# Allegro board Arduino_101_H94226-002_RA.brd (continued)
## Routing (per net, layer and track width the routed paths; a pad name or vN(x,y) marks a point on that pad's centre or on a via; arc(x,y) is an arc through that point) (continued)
PWM1/SS11_3V_IO5: length 27.2
  TOP w0.116: U12.G2 37.45,28.37 37.07,28.37 ; U12.A3 37.91,31.22 37.5,31.22 37.34,31.38
  TOP w0.15: v1(38.17,35.37) 37.82,35.02 37.82,34.4 37.02,33.6 37.02,32.53 37.32,32.23 37.32,31.55 v1(37.2,31.42) 37.22,31.4 37.32,31.4 37.34,31.38 ; 37.07,28.37 35.39,30.05 v1(35.17,30.05) ; U11.5 v1(51.74,36.65)
  BOTTOM w0.15: v1(35.17,30.05) 36.52,31.4 37.17,31.4 v1(37.2,31.42) ; v1(51.74,36.65) 51.74,36.53 51.05,35.83 44.84,35.83 44.72,35.95 43.07,35.95 42.32,35.2 38.34,35.2 v1(38.17,35.37)
PWM2/SS12_3V_IO6: length 27.4
  TOP w0.15: U11.4 v1(51.09,36.65) ; v1(34.62,35.1) 34.52,35 34.52,31.55 34.87,31.2 34.87,30.42 34.69,30.24 34.69,29.87 34.97,29.59 35.43,29.59 36.93,28.09 U12.G1
  BOTTOM w0.15: v1(34.62,35.1) 35.97,35.1 36.47,35.6 37.72,35.6 37.95,35.83 38.36,35.83 38.68,35.5 42.17,35.5 42.92,36.25 44.87,36.25 44.99,36.13 50.7,36.13 51.09,36.53 v1(51.09,36.65)
PWM3/SS13_3V_IO9: length 12.8
  TOP w0.116: 37.12,28.94 37.45,28.94 U12.F2
  TOP w0.15: 37.12,28.94 36.93,28.94 35.17,30.7 35.17,31.35 34.82,31.7 34.82,34.65 35.09,34.92 35.09,35.78 35.4,36.08 37.25,36.08 37.65,36.47 37.65,37.65
RST_SKETCH: length 96.2
  TOP w0.15: R23.2 29.31,44.59 30.17,45.45 33.47,45.45 v1(33.72,45.2) 33.74,45.17 U14.18 33.74,42.5 33.21,41.97 32.56,41.97 32.07,41.48 v1(32.07,41.32) ; J10.3 33.02,3.34 31.57,4.79 31.57,5.2 32.17,5.8 32.17,16.05 30.67,17.55 30.67,30.85 31.77,31.95 31.77,35.9 31.07,36.6 v1(31.07,39.3)
  BOTTOM w0.15: v1(33.72,45.2) 33.87,45.05 35.97,45.05 36.12,44.9 53.55,44.9 62.77,35.68 62.77,33.58 64.64,31.7 64.64,29.03 65.02,28.65 65.02,26.79 J12.5 ; v1(32.07,41.32) 32.07,40.3 v1(31.07,39.3)
RST_SKETCH_3V: length 25.3
  TOP w0.116: 45.82,28.33 45.87,28.38 46.47,28.38 U12.F22
  TOP w0.15: U14.3 v1(33.74,36.64) ; 45.82,28.33 45.72,28.33 45.6,28.2 44.28,28.2 43.76,28.72 43.76,31.21 44.06,31.51 44.06,33.74 44.52,34.2 44.52,37.65 v1(44.27,37.9)
  BOTTOM w0.15: v1(33.74,36.64) 34.98,36.64 35.76,37.42 36.01,37.42 36.68,38.09 39.58,38.09 39.92,37.75 41.22,37.75 41.27,37.8 44.17,37.8 v1(44.27,37.9)
RXD1/SS9_3V_IO0: length 24.7
  TOP w0.116: 45.87,26.64 46.05,26.64 46.07,26.66 46.46,26.66 U12.K22
  TOP w0.15: U11.10 v1(54.99,36.65) ; v1(43.45,34.25) 43.49,34.21 43.49,31.76 43.2,31.47 43.2,28.3 43.15,28.25 43.15,27.56 43.5,27.2 44.15,27.2 44.64,26.7 45.24,26.7 45.31,26.64 45.87,26.64
  BOTTOM w0.15: v1(43.45,34.25) 43.45,34.22 43.56,34.11 44.28,34.11 44.5,34.33 52.8,34.33 54.99,36.53 v1(54.99,36.65)
RXLED: length 12.3
  TOP w0.116: U12.C3 37.91,30.08 37.02,30.08
  TOP w0.15: v1(29.57,33.25) 29.41,33.25 D15.K ; v1(35.58,32.05) 35.77,31.86 35.77,30.9 36.59,30.08 37.02,30.08
  BOTTOM w0.15: v1(35.58,32.05) 35.4,32.23 30.44,32.23 29.57,33.1 v1(29.57,33.25)
SP0_CLK_MEM: length 20.5
  TOP w0.15: v1(41.12,27.55) 41.09,27.53 41.09,26.67 43.87,23.9 43.87,22.42 44.12,22.17 44.12,19.1 43.22,18.2 40.32,18.2 40.17,18.05 40.17,17.24 U201.6 ; v1(39.75,30.84) 39.69,30.78 39.69,30.7 39.36,30.37 U12.C4
  BOTTOM w0.15: v1(39.75,30.84) 39.69,30.78 39.69,30.7 39.4,30.41 39.4,29.23 41.07,27.55 v1(41.12,27.55)
SP0_CS0_MEM: length 29.9
  TOP w0.116: U12.B3 38.48,31.22 38.76,31.22 39.02,31.48 39.02,31.83 v1(39.05,31.85)
  TOP w0.15: U201.1 37.56,11.3 39.47,13.2 39.47,18.05 39.92,18.5 43.02,18.5 43.82,19.3 43.82,22.03 43.57,22.28 43.57,23.7 40.62,26.65 v1(40.62,27.08)
  BOTTOM w0.15: v1(40.62,27.08) 40.62,27.6 39.12,29.1 39.12,31.7 39.05,31.78 v1(39.05,31.85)
SP0_MISO_MEM: length 25.9
  TOP w0.15: v1(39.87,29.58) 39.85,29.56 39.71,29.56 39.48,29.79 38.65,29.79 U12.D4 ; v1(43.02,17.7) 43.22,17.7 44.42,18.9 44.42,22.28 44.17,22.53 44.17,24.07 41.57,26.67 v1(41.57,27.08) ; v1(42.97,16) 42.62,15.65 42.62,14.65 38.84,10.87 U201.2
  BOTTOM w0.15: v1(43.02,17.7) 43.22,17.5 43.22,16.25 v1(42.97,16) ; v1(41.57,27.08) 41.59,27.1 41.59,27.73 41.3,28.03 40.99,28.03 39.87,29.15 v1(39.87,29.58)
SP0_MOSI_MEM: length 20.6
  TOP w0.116: U12.D3 38.48,30.08 38.99,30.08 38.99,30.08 39.07,30.08
  TOP w0.15: 39.07,30.08 39.62,30.08 39.72,30.17 39.83,30.17 v1(39.87,30.21) ; v1(41.82,28.15) 41.82,28.15 42.03,27.94 42.03,26.64 44.47,24.2 44.47,22.62 44.72,22.38 44.72,18.65 43.27,17.2 42.82,17.2 42.22,17.8 41.52,17.8 41.38,17.66 U201.5
  BOTTOM w0.15: v1(39.87,30.21) 39.87,30.21 40.06,30.21 40.33,29.94 40.33,29.09 41.09,28.33 41.65,28.33 41.82,28.15 v1(41.82,28.15)
SP0_WP_MEM~: length 27.9
  TOP w0.15: v1(43.67,16) 43.67,13.24 R62.1 42.29,12.84 40.11,10.65 U201.3 ; v1(40.07,27.5) 40.07,26.72 43.27,23.52 43.27,22.17 43.52,21.92 43.52,19.5 43.02,19 v1(42.72,19) ; v1(38.42,31.98) 38.45,31.95 38.45,31.92 38.55,31.83 38.55,31.6 U12.A4
  BOTTOM w0.15: v1(42.72,19) 42.72,18.73 43.52,17.92 43.52,16.15 v1(43.67,16) ; v1(38.42,31.98) 38.42,31.65 38.84,31.23 38.84,28.98 40.07,27.75 v1(40.07,27.5)
TRIG_TRUE_D: length 45.3
  TOP w0.25: R75.1 17.42,37.89 U202.4 ; R75.1 17.31,37.74 16.57,37 16.57,35.6 15.87,34.9 U13.C3 ; R75.1 C55.1 19.89,37.74 R81.2 20.13,37.24 20.77,36.6 v1(22.02,36.6) ; v1(29.42,30.35) 29.52,30.25 29.52,17.05 30.87,15.7 v1(30.87,15.5) ; U10.13 v1(22.32,16.05)
  BOTTOM w0.25: v1(30.87,15.5) 22.87,15.5 v1(22.32,16.05) ; v1(29.42,30.35) 29.42,30.55 23.37,36.6 v1(22.02,36.6)
TXD1/SS8_3V_IO1: length 22.6
  TOP w0.15: v1(44.05,34.58) 43.97,34.5 43.97,34.08 43.77,33.88 43.77,31.62 43.48,31.33 43.48,28.19 43.42,28.13 43.42,27.69 43.64,27.47 44.3,27.47 44.77,27 45.34,27 45.42,26.91 45.96,26.91 45.99,26.95 U12.J21 ; U11.9 v1(54.34,36.65)
  BOTTOM w0.15: v1(44.05,34.58) 44.1,34.63 52.45,34.63 54.34,36.53 v1(54.34,36.65)
TXLED: length 21.1
  TOP w0.15: U12.D21 46.27,29.83 45.59,29.83 45.17,30.25 v1(44.87,30.25) ; v1(30.67,34.28) D14.K
  BOTTOM w0.15: v1(30.67,34.28) 32.12,32.83 36.17,32.83 36.39,33.05 38.86,33.05 39,32.91 39.48,32.91 40.15,32.24 40.15,31.89 40.82,31.22 41.3,31.22 41.65,30.88 43.7,30.88 44.32,30.25 v1(44.87,30.25)
USB_5P00_PWR: length 13.7
  TOP w0.3: U13.A3 14.33,35.34 ; U13.B3 15.17,35.46 C18.1
  TOP w0.5: 14.33,35.34 13.16,35.34
  TOP w0.7: 13.16,35.9 13.46,36.2 C18.1 ; 13.16,35.9 v1(12.17,35.9) 11.47,35.9 10.52,36.85 J17.1 ; 13.16,35.9 C42.1 R12.1
  BOTTOM w0.5: TPB19.1 12.87,35.35 12.72,35.35 v1(12.17,35.9)
USBDN_CONN: length 45.1
  TOP w0.116: U12.J23 47.48,26.66 47.86,26.66 48.05,26.48
  TOP w0.15: v1(48.58,26.22) 48.58,26.23 48.57,26.23 48.57,26.25 48.47,26.35 48.17,26.35 48.05,26.48
  TOP w0.889: R32.2 15.76,38.05 v1(16.42,38.05)
  BOTTOM w0.45: 48.15,26.2 48.54,26.2 48.56,26.22 v1(48.58,26.22)
  BOTTOM w0.5: 47.74,24.94 47.78,24.99 47.78,25.26 47.84,25.32 47.84,25.32 47.84,25.9 48.15,26.2
  BOTTOM w0.889: 47.74,24.94 46.28,23.48 44,23.48 43.43,24.05 38.32,24.05 37.62,24.75 27.72,24.75 24.57,27.9 24.57,30.56 17.08,38.05 v1(16.42,38.05) 15.52,38.05 TPB17.1
USBDP_CONN: length 43.4
  TOP w0.102: U12.J24 48.07,26.95
  TOP w0.15: 48.07,26.95 48.23,26.95 v1(48.34,26.83)
  TOP w0.889: R31.2 15.61,39.14 15.68,39.07 v1(16.42,39.07)
  BOTTOM w0.45: 47.87,26.83 v1(48.34,26.83)
  BOTTOM w0.5: 47.02,25.66 47.02,25.98 47.87,26.83
  BOTTOM w0.889: 47.02,25.66 45.86,24.5 44.42,24.5 43.85,25.07 38.74,25.07 38.04,25.77 28.14,25.77 25.59,28.32 25.59,30.98 17.51,39.07 v1(16.42,39.07) 15.5,39.07 TPB18.1
V_1P8_ESR3: length 8.4
  TOP w0.3: U12.P3 38.19,23.84 38.19,23.84 38.19,23.67
  TOP w0.35: 37.61,22.94 37.61,23.09 38.19,23.67
  TOP w0.4: 37.61,22.94 37.22,22.55
  TOP w0.5: C29.1 C30.1 35.53,19.64 35.77,19.88 L12.1 35.77,21.55 36.77,22.55 37.22,22.55
V_3P3SRC_VDD1: length 34.9
  TOP w0.65: 26.31,20.16 R63.2 28.07,19.96 28.07,18.4 ; 26.57,26.62 27.84,26.62 27.87,26.66 R58.2
  TOP w1: J10.2 30.48,3.34 29.57,4.25 29.57,15.2 28.17,16.6 28.17,18.3 U17.2
  BOTTOM w0.8: J10.2 30.51,2.54 32.17,4.2 33.9,4.2 J10.4
  vias: v1(19.57,25.2) v1(19.57,24.2) v1(19.57,23.2) v1(19.57,22.2) v1(19.57,21.2) v1(19.57,20.2) v1(20.32,25.7) v1(20.32,24.7) v1(20.32,23.7) v1(20.32,22.7) v1(20.32,21.7) v1(20.32,20.7) v1(20.32,19.7) v1(20.87,26.6) v1(21.32,25.95) v1(21.32,19.5) v1(21.82,26.6) v1(22.32,25.95) v1(22.32,19.5) v1(22.82,26.6) v1(23.32,25.95) v1(23.32,19.5) v1(23.82,26.6) v1(24.32,25.95) v1(24.32,19.5) v1(25.32,19.5) v1(26.32,19.5) v1(27.07,23.45) v1(27.07,22.5) v1(27.07,21.5) v1(27.07,20.6) v1(27.07,19.7)
V_3P5_VREFA: length 56.6
  TOP w0.35: v1(49.8,39.2) U11.2 49.8,36.38 52.15,34.02 v1(52.15,32.85) ; v1(52.07,22.48) 52.47,22.08 52.47,17.1 53.07,16.5 53.67,16.5 54.01,16.16 U15.2 54.01,14.84 ; U14.2 v1(33.09,39.12)
  TOP w0.5: v1(48.17,12.44) R34.2 R33.2 C43.1 ; 54.01,14.84 54.01,14.28 53.33,13.6 v1(51.67,13.6)
  BOTTOM w0.35: v1(52.07,22.48) 52.07,22.8 52.32,23.05 52.32,28.1 51.37,29.05 51.37,29.72 52.52,30.86 52.52,31.4 52.33,31.59 52.33,32.14 52.15,32.32 v1(52.15,32.85) ; v1(33.09,39.12) 33.73,39.75 40.92,39.75 41.37,39.3 49.7,39.3 v1(49.8,39.2)
  BOTTOM w0.5: v1(48.17,12.44) 50.51,12.44 v1(51.67,13.6)
V_5P00SRC_VDD1: length 180.3
  TOP w0.2: v1(21.37,16.7) 21.32,16.65 U10.14
  TOP w0.3: U13.B1 U13.A1 14.43,33.76
  TOP w0.5: v1(55.37,9.65) 55.76,9.26 R27.1 ; R28.1 30.21,40.76 29.57,41.4 v1(29.57,42.15) ; v1(47.43,42.48) 47.23,42.69 47.23,44.24 46.03,45.44 R29.1 ; C39.1 14.43,33.76
  TOP w0.6: R57.2 v1(13.67,31.4)
  TOP w0.65: v1(51.87,31.1) 52.12,31.1 53.62,32.6 v1(54.47,32.6) ; J12.2 66.17,30.98 65.34,31.8 60.67,31.8 v1(59.87,32.6)
  TOP w0.7: C39.1 R57.2 C49.1 14.43,28.91 ; R33.1 47.33,9.49 v1(47.37,9.45)
  TOP w0.8: v1(47.37,9.45) v1(47.37,5) v1(46.72,5)
  TOP w1: U17.3 16.46,20.42 14.43,22.44 14.43,28.91
  BOTTOM w0.2: v1(21.37,16.7) 20.87,17.2 19.67,17.2 v1(19.17,16.7)
  BOTTOM w0.5: v1(29.57,42.15) 30.51,42.15 31.08,42.73 33.74,42.73 34.39,42.08 36.8,42.08 37.07,42.35 41.18,42.35 42.99,40.54 44.29,40.54 45.42,41.67 46.63,41.67 v1(47.43,42.48)
  BOTTOM w0.6: v1(29.57,42.15) 27.17,42.15 26.42,41.4 12.67,41.4 11.07,39.8 11.07,35.2 13.67,32.6 v1(13.67,31.4)
  BOTTOM w0.65: v1(54.47,32.6) v1(59.87,32.6) ; v1(51.87,31.1) 50.75,29.98 50.75,28.76 51.62,27.89 51.62,25.9
  BOTTOM w0.8: 51.62,25.9 51.62,23.4 51.27,23.05 51.27,22.05 52.27,21.05 52.27,16 55.5,12.77 55.5,9.78 v1(55.37,9.65) 55.17,9.45 v1(47.37,9.45) ; 38.1,3.77 38.83,4.5 46.22,4.5 v1(46.72,5) v1(47.37,5) ; v1(15.67,17.7) v1(16.27,17.7) v1(15.67,18.3) v1(15.67,17.7)
  BOTTOM w1.5: v1(15.67,17.7) 14.46,16.49 14.46,10.81 15.52,9.75 15.52,7.55 18.47,4.6 25.57,4.6 26.17,5.2 29.72,5.2 31.02,6.5 35.37,6.5 38.1,3.77 J10.5
VSYS: length 32.4
  TOP w0.25: U12.N4 39.11,24.67 39.24,24.53 ; 39.42,25.7 39.37,25.75 38.97,25.75 38.91,25.81 U12.L4
  TOP w0.3: U12.P2 37.74,23.95
  TOP w0.35: 37.74,23.95 37.05,23.25
  TOP w0.5: 34.72,22.4 35.57,23.25 37.05,23.25 ; 34.72,22.4 34.52,22.2 C32.1 C31.1 34.17,20.9 34.72,21.45 v1(34.72,21.5) 34.72,22.4 ; 39.24,24.53 39.52,24.25 v1(39.52,22.25) 39.52,21.59 C33.1 ; 39.42,25.7 39.52,25.7 40.52,24.7 40.52,22.36 v1(40.63,22.25) C25.1 C26.1
  TOP w0.6: R63.1 v1(28.27,22.2)
  BOTTOM w0.6: v1(28.27,22.2) 29.27,22.2 29.97,21.5 v1(34.72,21.5) 38.77,21.5 v1(39.52,22.25) v1(40.63,22.25)
N137369: length 9.4
  TOP w0.3: ESD11.1 13.27,39.06
  TOP w0.889: R31.1 14.19,39.06 12.65,39.06 11.03,40.67 7.85,40.67 J17.3
N350266: length 21.1
  TOP w0.116: U12.E23 47.48,29.51 47.83,29.51 47.97,29.65 47.97,29.8 48.07,29.9
  TOP w0.15: R30.2 50.78,32.44 v1(50.17,33.05) ; 48.07,29.9 48.18,30.01 48.33,30.01 49.39,31.07 49.39,31.55 48.97,31.98 48.97,32.7 v1(48.77,32.9) ; v1(39.83,33.28) 39.86,33.24 39.86,31.99 38.8,30.94 U12.B4
  BOTTOM w0.15: v1(39.83,33.28) 39.83,32.99 40.09,32.73 41.11,32.73 42.06,31.78 46.05,31.78 46.27,32 46.27,32.35 46.92,33 48.27,33 48.37,32.9 v1(48.77,32.9) 50.02,32.9 v1(50.17,33.05)
N352539: length 12.5
  TOP w0.116: 45.87,25.48 46.1,25.48 46.14,25.52 46.46,25.52 U12.L22
  TOP w0.15: R24.2 48.74,22.64 v1(48.74,23.42) ; v1(44.65,25.48) 44.97,25.15 45.5,25.15 45.82,25.48 45.87,25.48
  BOTTOM w0.15: v1(48.74,23.42) 48.8,23.47 48.8,24.37 49.07,24.64 49.07,26.78 48.55,27.3 47.67,27.3 45.52,25.15 44.97,25.15 v1(44.65,25.48)
N364156: length 3.8
  TOP w0.3: U12.P4 38.64,23.42
  TOP w0.35: 38.64,23.42 38.16,22.94 38.16,22.59
  TOP w0.4: 38.16,22.59 37.97,22.4
  TOP w0.5: 37.97,22.4 L12.2
N380754: length 5.8
  TOP w0.25: U12.K1 36.79,26.38
  TOP w0.3: 36.55,26.51 36.69,26.38 36.79,26.38
  TOP w0.4: C35.1 33.57,30 34.7,28.88 35.12,28.88 35.71,28.29 35.71,27.35 36.55,26.51
N385382: length 1.2
  TOP w0.9: 60.77,20.34 RLC11.2
  TOP w1.016: RLC10.2 60.77,20.34
N385442: length 3.5
  TOP w0.6: R19.2 58.37,16.94
  TOP w1.016: RLC10.1 C37.2 58.37,16.94
N441562: length 7
  TOP w0.3: 13.27,38.04 ESD10.1
  TOP w0.889: J17.2 8.83,39.66 10.61,39.66 12.23,38.04 14.19,38.04 R32.1
N463771: length 4.2
  TOP w0.116: U12.N2 37.45,24.38 36.87,24.38
  TOP w0.15: C45.1 34.76,24.25 36.45,24.25 36.58,24.38 36.87,24.38
N498391: length 6.8
  TOP w0.116: U12.H23 47.48,27.8 48.07,27.8
  TOP w0.2: U12.G22 46.75,28.02 47.2,27.57 U12.H23
  TOP w0.25: 48.07,27.8 48.16,27.72 48.82,27.72 49.09,27.45 49.17,27.45
  TOP w0.4: 49.17,27.45 49.87,27.45 50.13,27.19 R35.1 C20.1
N521217: length 16.6
  TOP w0.25: U12.K4 38.95,26.38 v1(39.06,26.26)
  TOP w0.5: R59.1 26.21,29.3 v1(26.47,29.3) 27.31,29.3 C17.1
  BOTTOM w0.5: v1(26.47,29.3) 26.47,28.6 28.47,26.6 38.48,26.6 38.81,26.26 v1(39.06,26.26)
N616057: length 5.6
  TOP w0.25: U12.L1 37.09,25.81 37.04,25.75
  TOP w0.3: 37.04,25.75 36.52,25.75 36.37,25.9
  TOP w0.4: 36.37,25.9 35.17,27.1 35.17,28.05 34.87,28.35 34.48,28.35 34.47,28.35 34.12,28.7 C48.1
N656910: length 5.3
  TOP w0.35: U15.19 54.01,10.39 54.22,10.6 54.66,10.6 ; C51.1 R27.2 56.12,10.53 56.05,10.6 54.66,10.6 ; 54.66,10.6 U15.20
N656990: length 5.7
  TOP w0.35: 49.14,44.52 49.61,44.52 49.8,44.33 U11.19 ; 49.14,44.52 48.43,45.23 C53.1 R29.2 ; 49.14,44.52 U11.20
N657094: length 5.6
  TOP w0.35: C52.1 R28.2 31.98,42.04 32.45,42.5 ; 32.45,42.5 32.97,42.5 33.09,42.62 U14.19 ; 32.45,42.5 32.45,43.55
N692018: length 3.7
  TOP w0.4: SH10.1 17.71,32.4 R73.2 17.57,33.1 18.11,33.64 R74.1
N692192: length 1.5
  TOP w0.3: R74.2 16.33,34.5 U13.C2
N704436: length 1.4
  TOP w0.25: C15.1 23.56,13.95 U10.9
N704444: length 8.6
  TOP w0.25: v1(21.87,12.7) 21.82,12.75 U10.8 ; v1(16.67,13.9) 16.41,13.9 R71.1 15.97,14.34 R70.2
  BOTTOM w0.25: v1(16.67,13.9) 20.87,13.9 21.87,12.9 v1(21.87,12.7)
N724575: length 28.2
  TOP w0.15: v1(11.57,48) 11.18,48 10.33,47.15 SW12.2 ; R23.1 C41.1 v1(26.91,45.6)
  BOTTOM w0.15: v1(11.57,48) 12.37,47.2 23.77,47.2 25.37,45.6 v1(26.91,45.6)
N724587: length 11.3
  TOP w0.15: SW10.4 v1(4.63,24.83) ; R13.1 C19.1 9.08,26.07 9.07,26.06 v1(9.07,24.83) SW10.3
  BOTTOM w0.15: v1(4.63,24.83) v1(9.07,24.83)
N726409: length 1.2
  TOP w0.25: R10.2 59.47,36.61 59.48,36.61 D10.A
N726427: length 1.4
  TOP w0.15: R15.2 26.69,36.58 D14.A
N726455: length 1.3
  TOP w0.15: D15.A 26.62,34.29 R16.2
N765836: length 4
  TOP w0.25: R83.2 R82.1 C54.1 19.37,41.4 U202.1
N7255913: length 2.2
  TOP w0.15: R14.1 26.01,41.06 25,40.05 25,40.05 24.59,39.65 U16.4
N7256071: length 1.5
  TOP w0.15: R14.2 27.34,42.34 D13.A

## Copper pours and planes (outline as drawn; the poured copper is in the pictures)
GND on TOP (solid shape): 61.06,21.89 59.82,21.89 59.82,22.89 61.06,22.89
GND on TOP (solid shape): 26.97,17.7 26.97,17.1 26.87,17 21.67,17 21.57,17.1 21.17,17.1 20.97,16.9 20.97,15.65 21.02,15.6 21.92,15.6 21.97,15.55 21.97,13.8 21.52,13.8 21.52,13.05 20.17,13.05 20.17,16.6 20.47,16.9 20.47,18.3 20.97,18.8 25.87,18.8
GND on TOP (solid shape): 50.34,23.3 50.41,23.29 50.45,23.23 50.45,20.64 51.47,19.62 51.47,16.42 51.6,16.28 51.61,16.23 51.58,16.21 51.55,16.21 51.17,16.58 51.17,19.08 50.17,20.08 50.17,21.44 50.3,21.57 50.3,23.28
GND on TOP (solid shape): 51.85,8.48 52,8.34 51.99,8.32 52.02,8.09 52.17,7.93 52.17,7.85 52.18,7.77 52.23,7.71 53.24,6.7 58.13,6.7 61.06,3.77 61.06,3.53 61.04,3.47 60.98,3.45 60.73,3.42 60.5,3.33 60.48,3.31 57.68,6.1 53.19,6.1 51.79,7.51 51.8,7.53 51.77,7.76 51.61,7.93 51.61,8.75 51.85,8.75
GND on TOP (solid shape): 49.87,22.96 49.89,22.93 49.89,21.73 49.77,21.61 49.77,19.92 50.77,18.92 50.77,17.33 50.72,17.26 50.64,17.28 50.42,17.38 50.19,17.34 50.11,17.34 50.07,17.4 50.07,17.62 50.1,17.63 50.2,18.34 49.66,17.86 49.67,17.85 49.67,16.32 49.71,16.28 49.71,16.23 49.68,16.21 49.65,16.21 49.42,16.44 49.42,21.53 49.77,21.89 49.77,22.92 49.8,22.94 49.83,22.96
GND on TOP (solid shape): outline of 184 points within 62.53,4.12 68.08,11.12
GND on TOP (solid shape): outline of 184 points within 62.54,4.12 68.08,11.12
GND on TOP (solid shape): 38.09,36.49 40.1,34.49 40.1,33.69 40.06,33.63 39.99,33.62 39.48,33.44 39.66,32.93 39.66,32.08 39.49,31.91 39.42,31.89 39.36,31.94 39.16,32.16 38.87,32.13 38.8,32.12 38.76,32.16 38.24,32.31 38.08,31.79 38.09,31.74 38.06,31.7 37.98,31.6 37.96,31.49 37.96,31.47 37.85,31.36 37.56,31.36 37.52,31.39 37.52,31.47 37.52,32.31 37.22,32.61 37.22,33.52 38.02,34.32 38.02,34.94 38.09,35 38.1,34.99 38.44,35.64 37.79,35.3 37.8,35.28 37.63,35.12 37.61,35.14 37.39,35.23 37.16,35.17 37.09,35.16 37.05,35.22 36.6,35.52 36.29,35.08 36.3,35.06 35.86,34.63 35.86,32.46 35.82,32.39 35.75,32.39 35.59,32.43 35.43,32.4 35.36,32.41 35.32,32.47 35.32,34.42 35.62,34.72 35.62,35.22 35.65,35.23 35.91,35.43 35.92,35.76 35.92,35.84 35.98,35.87 37.33,35.87 37.85,36.39 37.85,36.87 38.09,36.87
GND on TOP (solid shape): outline of 10907 points within 0.5,0.5 68.08,52.84
GND on BOTTOM (solid shape): 48.05,31.93 48.07,31.9 48.05,31.88 47.94,31.6 48.05,31.33 48.08,31.3 47.67,30.88 47.67,29.32 48.62,28.37 48.62,28.14 48.63,28.12 48.64,28.08 48.61,28.06 48.49,28.06 48.49,28.06 47.36,28.06 47.34,28.05 46.91,27.63 45.55,27.63 45.52,27.66 45.53,27.68 45.48,27.94 45.26,28.11 45.21,28.16 45.23,28.24 45.54,28.54 45.54,29.16 45.54,29.21 45.54,29.27 45.54,29.38 45.95,29.79 45.95,30.44 47.15,31.64 47.15,31.99 47.31,32.15 47.83,32.15
GND on BOTTOM (solid shape): 40.44,30.73 40.49,30.8 40.57,30.79 40.64,30.73 41.1,30.73 41.45,30.37 43.51,30.37 44.14,29.74 44.14,29.72 44.16,29.54 44.26,29.39 44.28,29.34 44.26,29.28 44.14,29.06 44.19,28.81 43.99,28.6 43.59,28.6 43.29,28.3 43.05,28.3 42.2,29.15 41.75,29.15 41.74,29.18 41.4,29.48 41.02,29.24 40.96,29.2 40.89,29.22 40.82,29.28 40.82,30.24 40.44,30.62
GND on BOTTOM (solid shape): outline of 7217 points within 0.5,0.5 68.08,52.84
(no net) on TOP: 1,0.5 0.65,0.65 0.5,1 0.5,52.34 0.65,52.69 1,52.84 64.31,52.84 65.54,51.61 65.54,39.42 68.08,36.88 68.08,5.29 65.54,2.75 65.54,1 65.39,0.65 65.04,0.5 ; 23 cut-outs
(no net) on BOTTOM: 1,0.5 0.65,0.65 0.5,1 0.5,52.34 0.65,52.69 1,52.84 64.31,52.84 65.54,51.61 65.54,39.42 68.08,36.88 68.08,5.29 65.54,2.75 65.54,1 65.39,0.65 65.04,0.5 ; 19 cut-outs
DC_IN_5V_20V on TOP (solid shape): 22.47,10 23.07,10 23.42,9.65 23.42,8.75 23.07,8.4 22.47,8.4 22.27,8.2 20.07,8.2 20.07,10.2 22.27,10.2
DC_IN_5V_20V_FIL on TOP (solid shape): 27.77,8.4 24.37,8.4 24.02,8.75 24.02,9.65 24.37,10 25.37,10 25.77,10.4 27.77,10.4
Net_127 on TOP (solid shape): outline of 208 points within 14.59,-7.41 19.41,-2.59
Net_127 on TOP (solid shape): outline of 208 points within 16.59,56.93 21.41,61.75
Net_128 on BOTTOM (solid shape): outline of 208 points within 10.59,-7.41 15.41,-2.59
Net_128 on BOTTOM (solid shape): outline of 208 points within 12.59,56.93 17.41,61.75
Net_129 on BOTTOM (solid shape): outline of 208 points within 8.59,-71.75 13.41,-66.93
Net_130 on TOP (solid shape): outline of 208 points within 12.59,-71.75 17.41,-66.93
Net_131 on TOP (solid shape): outline of 208 points within 121.75,-71.75 126.57,-66.93
Net_132 on BOTTOM (solid shape): outline of 208 points within 125.75,-71.75 130.57,-66.93
Net_133 on BOTTOM (solid shape): outline of 208 points within 121.75,56.93 126.57,61.75
Net_133 on BOTTOM (solid shape): outline of 208 points within 123.75,-7.41 128.57,-2.59
Net_134 on TOP (solid shape): outline of 208 points within 117.75,56.93 122.57,61.75
Net_134 on TOP (solid shape): outline of 208 points within 119.75,-7.41 124.57,-2.59
V_3P3SRC_VDD1 on TOP (solid shape): 22.82,26.95 26.82,26.95 27.07,26.7 27.07,26.2 27.57,25.7 27.57,19.45 27.32,19.2 20.12,19.2 19.12,20.2 19.12,21.2 18.42,21.9 17.57,21.9 17.32,22.15 17.32,23.45 17.57,23.7 18.57,23.7 19.07,24.2 19.07,25.45 19.57,25.95 20.07,25.95 20.57,26.45 20.57,27.7 20.82,27.95 21.82,27.95
V_3P3SRC_VDD1 on BOTTOM (solid shape): 27.57,23.45 27.57,19.45 27.32,19.2 20.07,19.2 19.07,20.2 19.07,25.45 20.57,26.95 24.07,26.95
V_5P00SRC_VDD1 on TOP (solid shape): 18.62,20.95 18.62,19.95 19.87,18.7 19.87,17.15 19.47,16.75 19.47,16.6 19.27,16.4 18.82,16.4 18.72,16.3 15.57,16.3 14.37,17.5 14.37,18.4 15.57,19.6 15.57,21.2 15.77,21.4 18.17,21.4
N385382 on TOP (solid shape): 67.61,12.13 63.06,12.13 63.06,17.13 63.58,17.13 63.58,12.65 67.06,12.65 67.06,20.13 60.43,20.13 60.43,20.66 67.06,20.66 67.06,22.13 60.06,22.13 60.06,22.65 67.61,22.65
N544606 on TOP (solid shape): 26.92,16.25 26.92,15.85 27.97,14.8 27.97,12.5 27.67,12.2 25.77,12.2 25.37,12.6 25.37,13.4 24.47,14.3 22.12,14.3 22.12,15.6 22.17,15.65 22.57,15.65 23.32,16.4 26.77,16.4
N545273 on TOP (solid shape): 20.02,14.3 17.57,14.3 17.07,14.8 17.07,15.45 17.22,15.6 20.02,15.6

Small or netless copper shapes (teardrops, artwork), in the pictures only: 4 on TOP, 1 on BOTTOM

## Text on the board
BOTTOM: H94226-002 REV A
Ref Des/Silkscreen Bottom: 3 | 4 | 2 | 1
Ref Des/Silkscreen Top: MP H92726-002 | 180 Degree | 4 | 2 | 1 | 3 | 0 Degree
DIMENSION: D13 | D14 | D15 | D10 | ESD10 | ESD11 | U202 | D17 | U10 | L12 | J18 | U13 | L10 | SH10 | U16 | D18 | R13 | C19 | C42 | R12 | C11 | R31 | R32 | C18 | C39 | R57 | C49 | R71 | R74 | C36 | C14 | C13 | R81 | C54 | R82 | R83 | C50 | L13 | R59 | R15 | R16 | C41 | R23 | C35 | C48 | C23 | C24 | C28 | C45 | C32 | C31 | C25 | C26 | R29 | R24 | C53 | C22 | C21 | RLC12 | C46 | R19 | RLC11 | R70 | R73 | R75 | C55 | C16 | C15 | C12 | R14 | R77 | C17 | R65 | R58 | R63 | C52 | R28 | C29 | C30 | C44 | C33 | R62 | C43 | R34 | R33 | R30 | C47 | R35 | C20 | C38 | R27 | C51 | R18 | R10 | RLC10 | C37 | (3X) | (FAR SIDE) | QR CODE LABEL | J17 | J16 | SW12 | SW10 | J15 | U17 | J11 | U14 | J10 | U201 | U12 | U15 | U11 | J13 | J14 | SERIAL NO. LABEL | J12
PANEL_BOT: X | 2 | A | B | VIEWED FROM SECONDARY SIDE | MULTIPACK DWG, MAIN PCB, | XXXXXX BOARD XX | XXXXXX-001
User.5: PRODUCTIO RELEASE | A | 10 | 11 | 12 | NOTES: UNLESS OTHERWISE SPECIFIED: | 1. | 2. | 3 | 4. | 5. | 6 | 7. | 8 | 9 | CLEAR COPPER AND ADD TOP AND BOTTOM SOLDERMASK TO OPENING AREA (40mm X 6mm) | FOR THE BARCODE. | MARK IMAGE #(1,2,3,4) ON OUTRIGGER TOP SIDE APPROXIMATELY WHERE SHOWN. | USE MOUSE BITE DIMENSIONS AS SPECIFIED. | ITEM IDENTIFICATION NUMBER IS PARENT LINE ITEM NUMBER ON | ENGINEERING BILL OF MATERIAL. | DIMENSIONING AND TOLERANCING PER ANSI Y14.5M. | THE CENTER OF THESE HOLES ESTABLISH DATUM -A-. | DATUM -B- IS PERPENDICULAR TO DATUM -A- THROUGH THE CENTER OF THIS HOLE. | THIS DOCUMENT ALSO EXISTS ON ELECTRONIC MEDIA. | MARK "MP" IDENTIFICATION NUMBER, AND LETTERS (H94226-002) APPROXIMATELY | WHERE SHOWN ON TOP SIDE. | TYPICAL ROUTE SLOTS AS SPECIFIED PER GERBER OR CAD FILE. | OUTRIGGER SHOULD BE METALIZED. | THESE KIND OF AREAS TO BE FREE OF METALIZTION. | P. VALDEZ | M. KASHI | 11/09/15 | 1 | PANEL FIDUCIAL (6X) | 1MM FIDUCIAL | 2,54MM SOLDER MASK KEEPOUT | (4X) | 4 | 2 | (TYP) | (3X) | (2X) | B | VIEWED FROM PRIMARY SIDE | MULTIPACK DWG, MAIN PCB, | ARDUINO 101 BOARD | H94226-002
User.8: VIEWED FROM SECONDARY SIDE
User.9: TPB21 | PLAT_3P3 | TPB11 | SWD_SCL | TPB12 | TPB10 | SWD_SDA | TPB13 | GND | TPB22 | TPB15 | JTAG_TRST | JTAG_TDO | TPB16 | TPB14 | TPB23 | TPB18 | TPB17 | USBDP | USBDN | USB_5P00 | TPB19 | DC_IN_JACK | TPB20 | JTAG_TMS | JTAG_TCK | JTAG_TDI
User.14: SECONDARY SIDE PLATE AREA | SEL_ENIG_BOT.ART | 16
User.15: PRIMARY SIDE PLATE AREA | SEL_ENIG_TOP.ART | 15
User.32: 5. USE ASSEMBLY DRAWING AS REFERENCE FOR PIN 1 LOCATION AND | COMPONENT ORIENTATION MARKINGS.  SILKSCREEN MARKINGS MAY | BE MISSING OR INACCURATE. | VIEWED FROM PRIMARY SIDE | VIEWED FROM SECONDARY SIDE
User.34: DRILL TOP-BOT
User.35: NOTES: (UNLESS OTHERWISE SPECIFIED) | 1. PCB IS A 2-LAYER BOARD. | 1.1 PCB MATERIAL TO BE HALOGEN-FREE (BR<900PPM, CL<900PPM) FR4 UL 94V-0, | Tg 150C, FLAME RETARDANT GLASS. | 1.2 THE PCB MUST MEET HALOGEN-FREE REQUIREMENT AT REFLOW PEAK TEMPERTURE OF 255C. | DURATION IS 60 SECONDS MAX. | 1.3 MICROVIAS ON BGA PADS MUST BE COPPER-FILLED ON EXTERNAL LAYERS. | 1.4 Q.C. DIMENSION: OVERALL FINISHED THICKNESS IS 1.575MM (+/-10%). | 1.5 MEASUREMENT SHALL BE MADE FROM SOLDERMASK TO SOLDERMASK PER Q.C. LOCATION.  REFER | TO LAYER ORIENTATION AS SHOWN IN SECTION A-A FOR LAYER THICKNESS AND STACKUP. | 2. SURFACE FINISH:  ENIG | 2.1 OSP PER INTEL SPEC A84501 (ENTEK PLUS HT OR EQUIVALENT) | 2.2 ENIG THICKNESS TO BE 0.03 UM (1.2 MICROINCHES) MINIMUM IMMERSION GOLD | OVER 2.54 UM (100 MICROINCHES) MINIMUM ELECTROLESS NICKEL. | 3. SOLDERMASK REQUIREMENTS: REFER TO IPC-SM-840 TYPE B, CLASS 2. | 3.1 SOLDERMASK COLOR IS PANTONE 7474 OR AS CLOSE AS POSSIBLE, LP1, | OVER BARE COPPER [SMOBC] SEMI-MATTE FINISH, HALOGEN FREE. | 3.2 DO NOT COVER VIAS LOCATED WITHIN SURFACE MOUNT PADS OR TEST POINTS. | 3.3 DO NOT COVER VIAS INTENTIONALLY LEFT OPEN BY SUPPLIED ARTWORK OR ODB++ DATA. | 3.4 10 MIL DRILL VIAS TO HAVE SOLDERMASK CLEARANCE ON PRIMARY AND SECONDARY SIDES. | 4. LEGEND [SILKSCREEN] REQUIREMENTS: RoHS\HALOGEN FREE. | 4.1 MATERIAL: (WHITE) Taiyo S-200W OR EQUIVALENT. | 4.2 NO INK ON METAL EXCEPT IN SPECIFIED AREAS.  FABRICATOR MUST MODIFY SILKSCREEN | IMAGE AND REMOVE ANY WHITE EPOXY INK FROM EXPOSED METAL. PIN 1 MARKERS SHOULD | BE MOVED TO CLEAR EXPOSED METAL. | 5. FABRICATION PROCESS SHALL BE U.L. RECOGNIZED: | 5.1 THE PCB SHALL BE IDENTIFIED WITH MANUFACTURES LOGO, U.L. TYPE DESIGNATION, | AND DATE CODE AS INDICATED BY CALENDAR WORK WEEK AND YEAR (WWYY). | 5.2 PLACE IDENTIFICATION MARKINGS ON SECONDARY SIDE WHERE SHOWN. | 6. THIS BOARD HAS IMPEDANCE CONTROLLED REQUIREMENTS.  TRACE WIDTHS ARE CORRECT BY DESIGN | AND DESIRED IMPEDANCE VALUE MAY NOT BE FULLY ATTAINED.  IMPEDANCE TOLERANCE TO BE +/-10%. | 6.1 50 OHM IMPEDANCE MICROSTRIP TRACES ON TOP LAYER 1 TO BE 1.016 MM REFERENCED | TO GROUND ON BOTTOM LAYER. | 6.2 100 OHM IMPEDANCE DIFF PAIRS ON BOTTOM LAYER TO HAVE 0.889 MM TRACE WIDTHS WITH | 0.127MM SPACING AND REFERENCED TO GROUND ON TOP LAYER. | 7. ANTENNA LINE ON TOP SIDE SHORTED TO GROUND IS CORRECT BY DESIGN. | 8. DO NOT REMOVE SILKSCREEN FROM CLEARED SOLDER MASK AREA. OKAY TO PLACE INK OVER METAL PAD. | VIEWED FROM PRIMARY SIDE
User.36: VIEWED FROM SECONDARY SIDE
User.37: 0.020 MM | 0.036 MM | 1.463 MM | 1.575 MM | 1.575 MM +/-.10% SOLDERMASK TO SOLDERMASK | LAYER STACKUP FOR SINGLE PCB | SCALE : NONE | SOLDERMASK | CORE | (REFERENCE ONLY) | MASK_TOP..........PRIMARY SOLDERMASK | L01_TOP.....PRIMARY SIDE  .50 oz. Cu | L02_BOT...SECONDARY SIDE  .50 oz. Cu | MASK_BOT........SECONDARY SOLDERMASK
User.38: DC_IN_JACK | USB_5P00 | USBDP | USBDN | GND | JTAG_TDO | JTAG_TRST | SWD_SDA | SWD_SCL | PLAT_3P3 | JTAG_TDI | JTAG_TCK | JTAG_TMS
User.40: FIGURE | SIZE | 0.254 | 0.7 | 0.92 | 1.02 | 2.3 | 3.05 | 3.1 | 3.56 | 3.2 | 4.1 | DRILL CHART: TOP to BOTTOM | ALL UNITS ARE IN MILLIMETERS | TOLERANCE | +0.076/-0.254 | +0.076/-0.076 | +0.051/-0.051 | PLATED | NON-PLATED | QTY | 564 | 10 | 4 | 38 | 2 | 1
User.45: PRODUCTION RELEASE | A | P. VALDEZ | M. KASHI | 11/09/15 | 1 | VIEWED FROM PRIMARY SIDE | VIEWED FROM SECONDARY SIDE | TEST POINT DWG, MAIN PCB, | ARDUINO 101 BOARD | H94226-002
